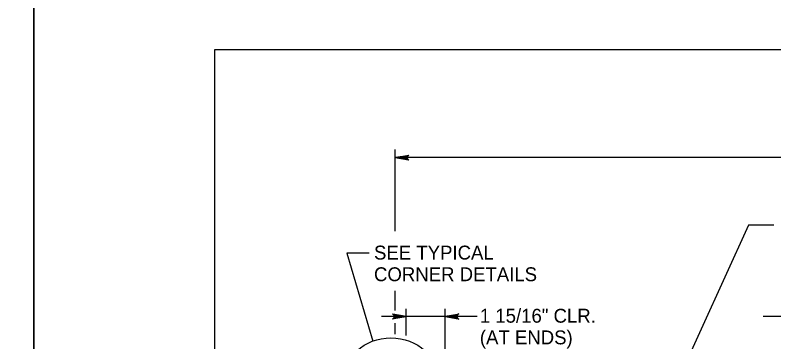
# Model space of a CAD drawing. Extents: x 2087776 to 2104538, y 970919 to 982612.
# Drawn here: x 2096040 to 2096578, y 980407 to 980639 of the extents above; entities that cross this region are included whole.
import ezdxf

# ---------------------------------------------------------------- set-up
doc = ezdxf.new("R2010")
doc.units = 0
doc.layers.add('1', color=7, linetype='Continuous')
doc.layers.add('PLT-BNDY', color=7, linetype='Continuous')

msp = doc.modelspace()

# ---------------------------------------------------------------- linework, layer by layer
at = {"layer": '1'}
for p, q in [((2096309.27, 980485.81), (2096309.27, 980543.7)), ((2097009.03, 980537.86), (2096309.27, 980537.86)), ((2096309.27, 980429.55), (2096309.27, 980443.52)), ((2096317.14, 980411.77), (2096317.14, 980430.64)), ((2096344.64, 980375.88), (2096344.64, 980430.64)), ((2096367.33, 980425.28), (2096299.66, 980425.28)), ((2096631.28, 980425.28), (2096570.03, 980425.28)), ((2096309.27, 980412.7), (2096309.27, 980420.55))]:
    msp.add_line(p, q, dxfattribs=at)
for points in [[(2098759.93, 978763.82), (2098759.93, 980614.22), (2096181.19, 980614.22), (2096181.19, 978763.82), (2098759.93, 978763.82), (2098759.93, 978850.3), (2098103.76, 978850.3), (2098103.76, 979062.5), (2098759.93, 979062.5), (2098759.93, 979157.53), (2098103.76, 979157.53), (2098103.76, 978763.82), (2098362.29, 978763.82), (2098362.29, 978850.3), (2098362.29, 978763.82), (2098614.92, 978763.82), (2098614.92, 978850.3), (2098614.92, 978809.9), (2098759.93, 978809.9)], [(2096309.27, 980537.86), (2096319.06, 980539.7), (2096318.68, 980539.43), (2096318.3, 980539.17), (2096318.11, 980538.85), (2096317.91, 980538.52), (2096317.86, 980538.19), (2096317.8, 980537.86), (2096317.86, 980537.53), (2096317.91, 980537.2), (2096318.11, 980536.88), (2096318.3, 980536.55), (2096318.68, 980536.29), (2096319.06, 980536.03), (2096309.27, 980537.86), (2096318.68, 980536.29), (2096318.3, 980536.55), (2096309.27, 980537.86), (2096318.11, 980536.88), (2096317.91, 980537.2), (2096309.27, 980537.86), (2096317.86, 980537.53), (2096317.8, 980537.86), (2096309.27, 980537.86), (2096317.86, 980538.19), (2096317.91, 980538.52), (2096309.27, 980537.86), (2096318.11, 980538.85), (2096318.3, 980539.17), (2096309.27, 980537.86), (2096318.68, 980539.43)], [(2096577.65, 980489.97), (2096559.72, 980489.97), (2096509.4, 980379.52)], [(2096290.87, 980470.19), (2096275.13, 980470.19), (2096293.36, 980407.84)], [(2096317.14, 980425.28), (2096307.36, 980423.44), (2096307.74, 980423.7), (2096308.11, 980423.96), (2096308.31, 980424.29), (2096308.5, 980424.62), (2096308.56, 980424.95), (2096308.61, 980425.28), (2096308.56, 980425.61), (2096308.5, 980425.93), (2096308.31, 980426.26), (2096308.11, 980426.59), (2096307.74, 980426.85), (2096307.36, 980427.11), (2096317.14, 980425.28), (2096307.74, 980426.85), (2096308.11, 980426.59), (2096317.14, 980425.28), (2096308.31, 980426.26), (2096308.5, 980425.93), (2096317.14, 980425.28), (2096308.56, 980425.61), (2096308.61, 980425.28), (2096317.14, 980425.28), (2096308.56, 980424.95), (2096308.5, 980424.62), (2096317.14, 980425.28), (2096308.31, 980424.29), (2096308.11, 980423.96), (2096317.14, 980425.28), (2096307.74, 980423.7)], [(2096344.64, 980425.28), (2096354.43, 980427.11), (2096354.05, 980426.85), (2096353.68, 980426.59), (2096353.48, 980426.26), (2096353.29, 980425.93), (2096353.23, 980425.61), (2096353.17, 980425.28), (2096353.23, 980424.95), (2096353.29, 980424.62), (2096353.48, 980424.29), (2096353.68, 980423.96), (2096354.05, 980423.7), (2096354.43, 980423.44), (2096344.64, 980425.28), (2096354.05, 980423.7), (2096353.68, 980423.96), (2096344.64, 980425.28), (2096353.48, 980424.29), (2096353.29, 980424.62), (2096344.64, 980425.28), (2096353.23, 980424.95), (2096353.17, 980425.28), (2096344.64, 980425.28), (2096353.23, 980425.61), (2096353.29, 980425.93), (2096344.64, 980425.28), (2096353.48, 980426.26), (2096353.68, 980426.59), (2096344.64, 980425.28), (2096354.05, 980426.85)]]:
    msp.add_lwpolyline(points, dxfattribs=at)
msp.add_ellipse((2096306.29, 980379.51), major_axis=(33.95, 0), ratio=0.902174, dxfattribs=at)
at = {"layer": 'PLT-BNDY'}
for points in [[(2093294.05, 980663.43), (2096053.23, 980663.43), (2096053.23, 978714.61), (2093294.05, 978714.61)], [(2096053.23, 980663.43), (2098812.42, 980663.43), (2098812.42, 978714.61), (2096053.23, 978714.61)]]:
    msp.add_lwpolyline(points, close=True, dxfattribs=at)

# ---------------------------------------------------------------- texts
at = {"layer": '1'}
for s, height, p in [('SEE TYPICAL', 9.8425, (2096294.29, 980465.64)), ('CORNER DETAILS', 9.8425, (2096294.29, 980450.29)), ('1 15/16" CLR.', 9.8425, (2096369.3, 980420.89)), ('(AT ENDS)', 9.843, (2096369.3, 980405.54))]:
    msp.add_text(s, height=height, dxfattribs=at).set_placement(p)

doc.saveas('drawing.dxf')
